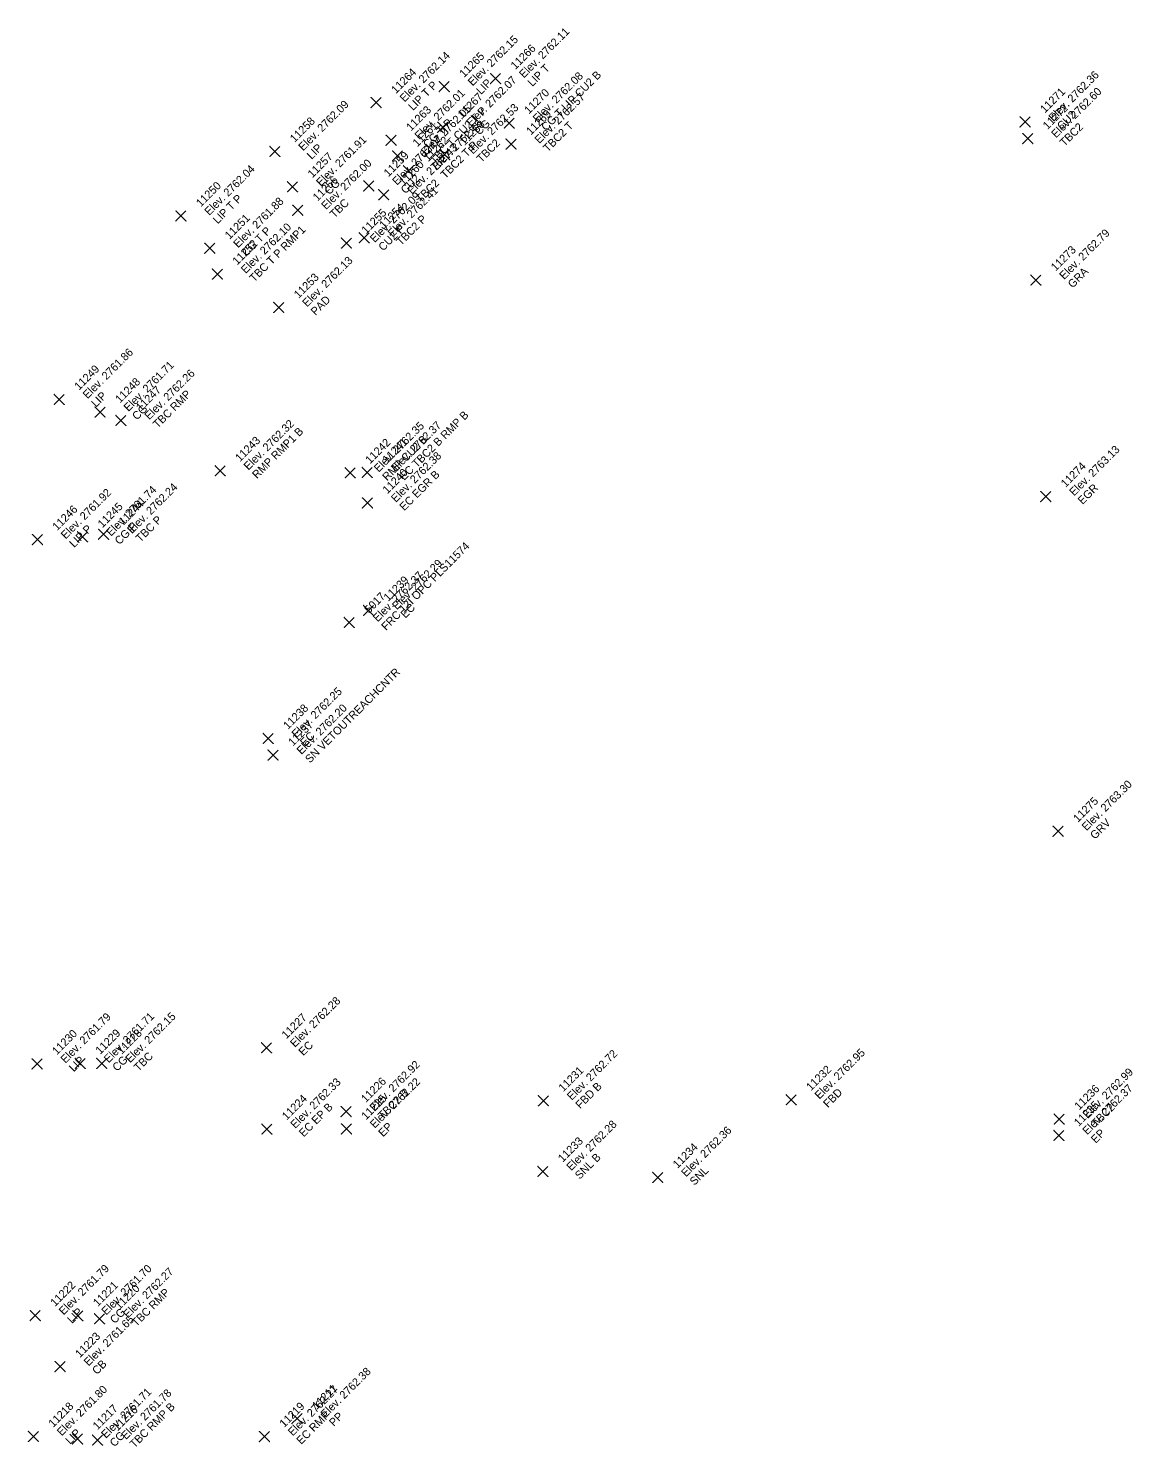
# Model space of a CAD drawing. Extents: x 2493999 to 2503109, y 700767 to 706646.
# Drawn here: x 2502307.24 to 2502340.35, y 701734.74 to 701777.28 of the extents above; entities that cross this region are included whole.
import ezdxf

# ---------------------------------------------------------------- set-up
doc = ezdxf.new("R2010")
doc.units = 0
doc.layers.add('ALG_CL_BLUE_Horiz', color=7, linetype='Continuous')
doc.layers.add('DES_SURFACE_Existing-Ground', color=7, linetype='Continuous')

msp = doc.modelspace()

# ---------------------------------------------------------------- linework, layer by layer
at = {"layer": 'ALG_CL_BLUE_Horiz'}
for points in [[(2502319.71, 701775.531), (2502319.56, 701775.681), (2502319.71, 701775.531), (2502319.56, 701775.381), (2502319.71, 701775.531), (2502319.86, 701775.381), (2502319.71, 701775.531), (2502319.86, 701775.681)], [(2502321.249, 701775.767), (2502321.099, 701775.917), (2502321.249, 701775.767), (2502321.099, 701775.617), (2502321.249, 701775.767), (2502321.399, 701775.617), (2502321.249, 701775.767), (2502321.399, 701775.917)], [(2502317.668, 701775.048), (2502317.518, 701775.198), (2502317.668, 701775.048), (2502317.518, 701774.898), (2502317.668, 701775.048), (2502317.818, 701774.898), (2502317.668, 701775.048), (2502317.818, 701775.198)], [(2502319.663, 701774.312), (2502319.513, 701774.462), (2502319.663, 701774.312), (2502319.513, 701774.162), (2502319.663, 701774.312), (2502319.813, 701774.162), (2502319.663, 701774.312), (2502319.813, 701774.462)], [(2502321.658, 701774.436), (2502321.508, 701774.586), (2502321.658, 701774.436), (2502321.508, 701774.286), (2502321.658, 701774.436), (2502321.808, 701774.286), (2502321.658, 701774.436), (2502321.808, 701774.586)], [(2502337.128, 701774.468), (2502336.978, 701774.618), (2502337.128, 701774.468), (2502336.978, 701774.318), (2502337.128, 701774.468), (2502337.278, 701774.318), (2502337.128, 701774.468), (2502337.278, 701774.618)], [(2502318.116, 701773.921), (2502317.966, 701774.071), (2502318.116, 701773.921), (2502317.966, 701773.771), (2502318.116, 701773.921), (2502318.266, 701773.771), (2502318.116, 701773.921), (2502318.266, 701774.071)], [(2502337.208, 701773.97), (2502337.058, 701774.12), (2502337.208, 701773.97), (2502337.058, 701773.82), (2502337.208, 701773.97), (2502337.358, 701773.82), (2502337.208, 701773.97), (2502337.358, 701774.12)], [(2502314.63, 701773.584), (2502314.48, 701773.734), (2502314.63, 701773.584), (2502314.48, 701773.434), (2502314.63, 701773.584), (2502314.78, 701773.434), (2502314.63, 701773.584), (2502314.78, 701773.734)], [(2502318.308, 701773.45), (2502318.158, 701773.6), (2502318.308, 701773.45), (2502318.158, 701773.3), (2502318.308, 701773.45), (2502318.458, 701773.3), (2502318.308, 701773.45), (2502318.458, 701773.6)], [(2502319.722, 701773.488), (2502319.572, 701773.638), (2502319.722, 701773.488), (2502319.572, 701773.338), (2502319.722, 701773.488), (2502319.872, 701773.338), (2502319.722, 701773.488), (2502319.872, 701773.638)], [(2502321.714, 701773.804), (2502321.564, 701773.954), (2502321.714, 701773.804), (2502321.564, 701773.654), (2502321.714, 701773.804), (2502321.864, 701773.654), (2502321.714, 701773.804), (2502321.864, 701773.954)], [(2502318.638, 701773.006), (2502318.488, 701773.156), (2502318.638, 701773.006), (2502318.488, 701772.856), (2502318.638, 701773.006), (2502318.788, 701772.856), (2502318.638, 701773.006), (2502318.788, 701773.156)], [(2502317.444, 701772.552), (2502317.294, 701772.702), (2502317.444, 701772.552), (2502317.294, 701772.402), (2502317.444, 701772.552), (2502317.594, 701772.402), (2502317.444, 701772.552), (2502317.594, 701772.702)], [(2502315.162, 701772.523), (2502315.012, 701772.673), (2502315.162, 701772.523), (2502315.012, 701772.373), (2502315.162, 701772.523), (2502315.312, 701772.373), (2502315.162, 701772.523), (2502315.312, 701772.673)], [(2502317.896, 701772.285), (2502317.746, 701772.435), (2502317.896, 701772.285), (2502317.746, 701772.135), (2502317.896, 701772.285), (2502318.046, 701772.135), (2502317.896, 701772.285), (2502318.046, 701772.435)], [(2502315.317, 701771.821), (2502315.167, 701771.971), (2502315.317, 701771.821), (2502315.167, 701771.671), (2502315.317, 701771.821), (2502315.467, 701771.671), (2502315.317, 701771.821), (2502315.467, 701771.971)], [(2502311.814, 701771.648), (2502311.664, 701771.798), (2502311.814, 701771.648), (2502311.664, 701771.498), (2502311.814, 701771.648), (2502311.964, 701771.498), (2502311.814, 701771.648), (2502311.964, 701771.798)], [(2502316.775, 701770.836), (2502316.625, 701770.986), (2502316.775, 701770.836), (2502316.625, 701770.686), (2502316.775, 701770.836), (2502316.925, 701770.686), (2502316.775, 701770.836), (2502316.925, 701770.986)], [(2502317.31, 701770.996), (2502317.16, 701771.146), (2502317.31, 701770.996), (2502317.16, 701770.846), (2502317.31, 701770.996), (2502317.46, 701770.846), (2502317.31, 701770.996), (2502317.46, 701771.146)], [(2502312.677, 701770.679), (2502312.527, 701770.829), (2502312.677, 701770.679), (2502312.527, 701770.529), (2502312.677, 701770.679), (2502312.827, 701770.529), (2502312.677, 701770.679), (2502312.827, 701770.829)], [(2502312.907, 701769.906), (2502312.757, 701770.056), (2502312.907, 701769.906), (2502312.757, 701769.756), (2502312.907, 701769.906), (2502313.057, 701769.756), (2502312.907, 701769.906), (2502313.057, 701770.056)], [(2502337.451, 701769.725), (2502337.301, 701769.875), (2502337.451, 701769.725), (2502337.301, 701769.575), (2502337.451, 701769.725), (2502337.601, 701769.575), (2502337.451, 701769.725), (2502337.601, 701769.875)], [(2502314.748, 701768.904), (2502314.598, 701769.054), (2502314.748, 701768.904), (2502314.598, 701768.754), (2502314.748, 701768.904), (2502314.898, 701768.754), (2502314.748, 701768.904), (2502314.898, 701769.054)], [(2502308.164, 701766.149), (2502308.014, 701766.299), (2502308.164, 701766.149), (2502308.014, 701765.999), (2502308.164, 701766.149), (2502308.314, 701765.999), (2502308.164, 701766.149), (2502308.314, 701766.299)], [(2502309.391, 701765.766), (2502309.241, 701765.916), (2502309.391, 701765.766), (2502309.241, 701765.616), (2502309.391, 701765.766), (2502309.541, 701765.616), (2502309.391, 701765.766), (2502309.541, 701765.916)], [(2502310.014, 701765.518), (2502309.864, 701765.668), (2502310.014, 701765.518), (2502309.864, 701765.368), (2502310.014, 701765.518), (2502310.164, 701765.368), (2502310.014, 701765.518), (2502310.164, 701765.668)], [(2502312.99, 701764.007), (2502312.84, 701764.157), (2502312.99, 701764.007), (2502312.84, 701763.857), (2502312.99, 701764.007), (2502313.14, 701763.857), (2502312.99, 701764.007), (2502313.14, 701764.157)], [(2502316.892, 701763.945), (2502316.742, 701764.095), (2502316.892, 701763.945), (2502316.742, 701763.795), (2502316.892, 701763.945), (2502317.042, 701763.795), (2502316.892, 701763.945), (2502317.042, 701764.095)], [(2502317.403, 701763.958), (2502317.253, 701764.108), (2502317.403, 701763.958), (2502317.253, 701763.808), (2502317.403, 701763.958), (2502317.553, 701763.808), (2502317.403, 701763.958), (2502317.553, 701764.108)], [(2502337.749, 701763.234), (2502337.599, 701763.384), (2502337.749, 701763.234), (2502337.599, 701763.084), (2502337.749, 701763.234), (2502337.899, 701763.084), (2502337.749, 701763.234), (2502337.899, 701763.384)], [(2502317.408, 701763.044), (2502317.258, 701763.194), (2502317.408, 701763.044), (2502317.258, 701762.894), (2502317.408, 701763.044), (2502317.558, 701762.894), (2502317.408, 701763.044), (2502317.558, 701763.194)], [(2502307.508, 701761.942), (2502307.358, 701762.092), (2502307.508, 701761.942), (2502307.358, 701761.792), (2502307.508, 701761.942), (2502307.658, 701761.792), (2502307.508, 701761.942), (2502307.658, 701762.092)], [(2502308.866, 701762.026), (2502308.716, 701762.176), (2502308.866, 701762.026), (2502308.716, 701761.876), (2502308.866, 701762.026), (2502309.016, 701761.876), (2502308.866, 701762.026), (2502309.016, 701762.176)], [(2502309.496, 701762.102), (2502309.346, 701762.252), (2502309.496, 701762.102), (2502309.346, 701761.952), (2502309.496, 701762.102), (2502309.646, 701761.952), (2502309.496, 701762.102), (2502309.646, 701762.252)], [(2502317.439, 701759.82), (2502317.289, 701759.97), (2502317.439, 701759.82), (2502317.289, 701759.67), (2502317.439, 701759.82), (2502317.589, 701759.67), (2502317.439, 701759.82), (2502317.589, 701759.97)], [(2502316.862, 701759.456), (2502316.712, 701759.606), (2502316.862, 701759.456), (2502316.712, 701759.306), (2502316.862, 701759.456), (2502317.012, 701759.306), (2502316.862, 701759.456), (2502317.012, 701759.606)], [(2502314.43, 701755.978), (2502314.28, 701756.128), (2502314.43, 701755.978), (2502314.28, 701755.828), (2502314.43, 701755.978), (2502314.58, 701755.828), (2502314.43, 701755.978), (2502314.58, 701756.128)], [(2502314.579, 701755.479), (2502314.429, 701755.629), (2502314.579, 701755.479), (2502314.429, 701755.329), (2502314.579, 701755.479), (2502314.729, 701755.329), (2502314.579, 701755.479), (2502314.729, 701755.629)], [(2502338.12, 701753.193), (2502337.97, 701753.343), (2502338.12, 701753.193), (2502337.97, 701753.043), (2502338.12, 701753.193), (2502338.27, 701753.043), (2502338.12, 701753.193), (2502338.27, 701753.343)], [(2502314.381, 701746.7), (2502314.231, 701746.85), (2502314.381, 701746.7), (2502314.231, 701746.55), (2502314.381, 701746.7), (2502314.531, 701746.55), (2502314.381, 701746.7), (2502314.531, 701746.85)], [(2502307.498, 701746.217), (2502307.348, 701746.367), (2502307.498, 701746.217), (2502307.348, 701746.067), (2502307.498, 701746.217), (2502307.648, 701746.067), (2502307.498, 701746.217), (2502307.648, 701746.367)], [(2502308.796, 701746.232), (2502308.646, 701746.382), (2502308.796, 701746.232), (2502308.646, 701746.082), (2502308.796, 701746.232), (2502308.946, 701746.082), (2502308.796, 701746.232), (2502308.946, 701746.382)], [(2502309.441, 701746.231), (2502309.291, 701746.381), (2502309.441, 701746.231), (2502309.291, 701746.081), (2502309.441, 701746.231), (2502309.591, 701746.081), (2502309.441, 701746.231), (2502309.591, 701746.381)], [(2502322.686, 701745.11), (2502322.536, 701745.26), (2502322.686, 701745.11), (2502322.536, 701744.96), (2502322.686, 701745.11), (2502322.836, 701744.96), (2502322.686, 701745.11), (2502322.836, 701745.26)], [(2502330.114, 701745.142), (2502329.964, 701745.292), (2502330.114, 701745.142), (2502329.964, 701744.992), (2502330.114, 701745.142), (2502330.264, 701744.992), (2502330.114, 701745.142), (2502330.264, 701745.292)], [(2502316.764, 701744.785), (2502316.614, 701744.935), (2502316.764, 701744.785), (2502316.614, 701744.635), (2502316.764, 701744.785), (2502316.914, 701744.635), (2502316.764, 701744.785), (2502316.914, 701744.935)], [(2502338.155, 701744.563), (2502338.005, 701744.713), (2502338.155, 701744.563), (2502338.005, 701744.413), (2502338.155, 701744.563), (2502338.305, 701744.413), (2502338.155, 701744.563), (2502338.305, 701744.713)], [(2502314.392, 701744.263), (2502314.242, 701744.413), (2502314.392, 701744.263), (2502314.242, 701744.113), (2502314.392, 701744.263), (2502314.542, 701744.113), (2502314.392, 701744.263), (2502314.542, 701744.413)], [(2502316.774, 701744.268), (2502316.624, 701744.418), (2502316.774, 701744.268), (2502316.624, 701744.118), (2502316.774, 701744.268), (2502316.924, 701744.118), (2502316.774, 701744.268), (2502316.924, 701744.418)], [(2502338.143, 701744.073), (2502337.993, 701744.223), (2502338.143, 701744.073), (2502337.993, 701743.923), (2502338.143, 701744.073), (2502338.293, 701743.923), (2502338.143, 701744.073), (2502338.293, 701744.223)], [(2502322.668, 701742.995), (2502322.518, 701743.145), (2502322.668, 701742.995), (2502322.518, 701742.845), (2502322.668, 701742.995), (2502322.818, 701742.845), (2502322.668, 701742.995), (2502322.818, 701743.145)], [(2502326.111, 701742.814), (2502325.961, 701742.964), (2502326.111, 701742.814), (2502325.961, 701742.664), (2502326.111, 701742.814), (2502326.261, 701742.664), (2502326.111, 701742.814), (2502326.261, 701742.964)], [(2502307.445, 701738.67), (2502307.295, 701738.82), (2502307.445, 701738.67), (2502307.295, 701738.52), (2502307.445, 701738.67), (2502307.595, 701738.52), (2502307.445, 701738.67), (2502307.595, 701738.82)], [(2502308.725, 701738.665), (2502308.575, 701738.815), (2502308.725, 701738.665), (2502308.575, 701738.515), (2502308.725, 701738.665), (2502308.875, 701738.515), (2502308.725, 701738.665), (2502308.875, 701738.815)], [(2502309.375, 701738.575), (2502309.225, 701738.725), (2502309.375, 701738.575), (2502309.225, 701738.425), (2502309.375, 701738.575), (2502309.525, 701738.425), (2502309.375, 701738.575), (2502309.525, 701738.725)], [(2502308.191, 701737.138), (2502308.041, 701737.288), (2502308.191, 701737.138), (2502308.041, 701736.988), (2502308.191, 701737.138), (2502308.341, 701736.988), (2502308.191, 701737.138), (2502308.341, 701737.288)], [(2502315.294, 701735.582), (2502315.144, 701735.732), (2502315.294, 701735.582), (2502315.144, 701735.432), (2502315.294, 701735.582), (2502315.444, 701735.432), (2502315.294, 701735.582), (2502315.444, 701735.732)], [(2502307.388, 701735.043), (2502307.238, 701735.193), (2502307.388, 701735.043), (2502307.238, 701734.893), (2502307.388, 701735.043), (2502307.538, 701734.893), (2502307.388, 701735.043), (2502307.538, 701735.193)], [(2502308.716, 701734.969), (2502308.566, 701735.119), (2502308.716, 701734.969), (2502308.566, 701734.819), (2502308.716, 701734.969), (2502308.866, 701734.819), (2502308.716, 701734.969), (2502308.866, 701735.119)], [(2502309.316, 701734.934), (2502309.166, 701735.084), (2502309.316, 701734.934), (2502309.166, 701734.784), (2502309.316, 701734.934), (2502309.466, 701734.784), (2502309.316, 701734.934), (2502309.466, 701735.084)], [(2502314.317, 701735.041), (2502314.167, 701735.191), (2502314.317, 701735.041), (2502314.167, 701734.891), (2502314.317, 701735.041), (2502314.467, 701734.891), (2502314.317, 701735.041), (2502314.467, 701735.191)]]:
    msp.add_lwpolyline(points, dxfattribs=at)

# ---------------------------------------------------------------- texts
at = {"layer": 'DES_SURFACE_Existing-Ground'}
for s, p in [('Elev. 2762.15', (2502320.559, 701775.531)), ('Elev. 2762.11', (2502322.098, 701775.767)), ('Elev. 2762.14', (2502318.517, 701775.048)), ('11265', (2502320.304, 701775.786)), ('11266', (2502321.843, 701776.022)), ('LIP T', (2502322.352, 701775.512)), ('11264', (2502318.262, 701775.303)), ('LIP T P', (2502318.771, 701774.793)), ('Elev. 2762.07', (2502320.512, 701774.312)), ('LIP', (2502320.813, 701775.276)), ('Elev. 2762.08', (2502322.507, 701774.436)), ('CG T LIP CU2 B', (2502322.761, 701774.181)), ('Elev. 2762.36', (2502337.977, 701774.468)), ('Elev. 2762.01', (2502318.965, 701773.921)), ('11267', (2502320.257, 701774.567)), ('11270', (2502322.252, 701774.691)), ('Elev. 2762.57', (2502322.563, 701773.804)), ('11271', (2502337.722, 701774.723)), ('Elev. 2762.60', (2502338.057, 701773.97)), ('Elev. 2762.09', (2502315.479, 701773.584)), ('11263', (2502318.71, 701774.176)), ('Elev. 2762.05', (2502319.157, 701773.45)), ('TBC T CU2 T P', (2502319.411, 701773.195)), ('Elev. 2762.53', (2502320.571, 701773.488)), ('11269', (2502322.308, 701774.059)), ('11272', (2502337.802, 701774.225)), ('11258', (2502315.224, 701773.839)), ('11261', (2502318.902, 701773.705)), ('CG T P', (2502319.219, 701773.666)), ('Elev. 2762.46', (2502319.487, 701773.006)), ('11268', (2502320.316, 701773.743)), ('CG', (2502320.766, 701774.057)), ('TBC2 T', (2502322.817, 701773.549)), ('CU2', (2502338.231, 701774.213)), ('TBC2', (2502338.311, 701773.715)), ('Elev. 2761.91', (2502316.011, 701772.523)), ('Elev. 2762.07', (2502318.293, 701772.552)), ('11262', (2502319.232, 701773.261)), ('LIP', (2502315.733, 701773.329)), ('11257', (2502315.756, 701772.778)), ('11259', (2502318.038, 701772.807)), ('Elev. 2762.43', (2502318.745, 701772.285)), ('TBC2 T P', (2502319.741, 701772.751)), ('TBC2', (2502320.825, 701773.233)), ('Elev. 2762.04', (2502312.663, 701771.648)), ('Elev. 2762.00', (2502316.166, 701771.821)), ('11260', (2502318.49, 701772.54)), ('11256', (2502315.911, 701772.076)), ('CG', (2502316.265, 701772.268)), ('CU2', (2502318.547, 701772.297)), ('TBC2', (2502318.999, 701772.03)), ('11250', (2502312.408, 701771.903)), ('LIP T P', (2502312.917, 701771.393)), ('Elev. 2762.09', (2502317.624, 701770.836)), ('Elev. 2762.41', (2502318.159, 701770.996)), ('Elev. 2761.88', (2502313.526, 701770.679)), ('TBC', (2502316.42, 701771.566)), ('11255', (2502317.369, 701771.091)), ('11254', (2502317.904, 701771.251)), ('11251', (2502313.271, 701770.934)), ('Elev. 2762.10', (2502313.756, 701769.906)), ('TBC2 P', (2502318.413, 701770.741)), ('CG T P', (2502313.78, 701770.424)), ('TBC T P RMP1', (2502314.01, 701769.651)), ('CU2 P', (2502317.878, 701770.581)), ('Elev. 2762.79', (2502338.3, 701769.725)), ('11252', (2502313.501, 701770.161)), ('11273', (2502338.045, 701769.98)), ('Elev. 2762.13', (2502315.597, 701768.904)), ('11253', (2502315.342, 701769.159)), ('GRA', (2502338.554, 701769.47)), ('PAD', (2502315.851, 701768.649)), ('Elev. 2761.86', (2502309.013, 701766.149)), ('11249', (2502308.758, 701766.404)), ('Elev. 2761.71', (2502310.24, 701765.766)), ('11248', (2502309.985, 701766.021)), ('Elev. 2762.26', (2502310.863, 701765.518)), ('LIP', (2502309.267, 701765.894)), ('11247', (2502310.608, 701765.773)), ('TBC RMP', (2502311.117, 701765.263)), ('CG', (2502310.494, 701765.511)), ('Elev. 2762.32', (2502313.839, 701764.007)), ('Elev. 2762.35', (2502317.741, 701763.945)), ('Elev. 2762.37', (2502318.252, 701763.958)), ('EC TBC2 B RMP B', (2502318.506, 701763.703)), ('RMP RMP1 B', (2502314.093, 701763.752)), ('RMP CU2 B', (2502317.995, 701763.69)), ('11243', (2502313.584, 701764.262)), ('11242', (2502317.486, 701764.2)), ('11241', (2502317.997, 701764.213)), ('Elev. 2763.13', (2502338.598, 701763.234)), ('Elev. 2762.38', (2502318.257, 701763.044)), ('11274', (2502338.343, 701763.489)), ('11240', (2502318.002, 701763.299)), ('EC EGR B', (2502318.511, 701762.789)), ('Elev. 2761.92', (2502308.357, 701761.942)), ('Elev. 2761.74', (2502309.715, 701762.026)), ('Elev. 2762.24', (2502310.345, 701762.102)), ('EGR', (2502338.852, 701762.979)), ('11246', (2502308.102, 701762.197)), ('11245', (2502309.46, 701762.281)), ('11244', (2502310.09, 701762.357)), ('TBC P', (2502310.599, 701761.847)), ('LIP P', (2502308.611, 701761.687)), ('CG P', (2502309.969, 701761.771)), ('FRC 12I OPC PLS11574', (2502317.965, 701759.201)), ('Elev. 2762.29', (2502318.288, 701759.82)), ('Elev. 2762.37', (2502317.711, 701759.456)), ('11239', (2502318.033, 701760.075)), ('5017', (2502317.456, 701759.711)), ('EC', (2502318.542, 701759.565)), ('SN VETOUTREACHCNTR', (2502315.682, 701755.224)), ('Elev. 2762.25', (2502315.279, 701755.978)), ('11238', (2502315.024, 701756.233)), ('Elev. 2762.20', (2502315.428, 701755.479)), ('11237', (2502315.173, 701755.734)), ('EC', (2502315.533, 701755.723)), ('Elev. 2763.30', (2502338.969, 701753.193)), ('11275', (2502338.714, 701753.448)), ('GRV', (2502339.223, 701752.938)), ('Elev. 2762.28', (2502315.23, 701746.7)), ('Elev. 2761.79', (2502308.347, 701746.217)), ('Elev. 2761.71', (2502309.645, 701746.232)), ('Elev. 2762.15', (2502310.29, 701746.231)), ('11227', (2502314.975, 701746.955)), ('11230', (2502308.092, 701746.472)), ('11229', (2502309.39, 701746.487)), ('11228', (2502310.035, 701746.486)), ('EC', (2502315.484, 701746.445)), ('LIP', (2502308.601, 701745.962)), ('CG', (2502309.899, 701745.977)), ('TBC', (2502310.544, 701745.976)), ('Elev. 2762.72', (2502323.535, 701745.11)), ('Elev. 2762.95', (2502330.963, 701745.142)), ('Elev. 2762.92', (2502317.613, 701744.785)), ('11231', (2502323.28, 701745.365)), ('11232', (2502330.708, 701745.397)), ('Elev. 2762.99', (2502339.004, 701744.563)), ('Elev. 2762.33', (2502315.241, 701744.263)), ('11226', (2502317.358, 701745.04)), ('Elev. 2762.22', (2502317.623, 701744.268)), ('TBC2 B', (2502317.867, 701744.53)), ('FBD B', (2502323.789, 701744.855)), ('11236', (2502338.749, 701744.818)), ('Elev. 2762.37', (2502338.992, 701744.073)), ('11224', (2502314.986, 701744.518)), ('EC EP B', (2502315.495, 701744.008)), ('11225', (2502317.368, 701744.523)), ('FBD', (2502331.217, 701744.887)), ('11235', (2502338.737, 701744.328)), ('TBC2', (2502339.258, 701744.308)), ('EP', (2502317.877, 701744.013)), ('Elev. 2762.28', (2502323.517, 701742.995)), ('Elev. 2762.36', (2502326.96, 701742.814)), ('EP', (2502339.246, 701743.818)), ('11233', (2502323.262, 701743.25)), ('11234', (2502326.705, 701743.069)), ('SNL B', (2502323.771, 701742.74)), ('SNL', (2502327.214, 701742.559)), ('Elev. 2761.79', (2502308.294, 701738.67)), ('Elev. 2761.70', (2502309.574, 701738.665)), ('Elev. 2762.27', (2502310.224, 701738.575)), ('11222', (2502308.039, 701738.925)), ('11221', (2502309.319, 701738.92)), ('11220', (2502309.969, 701738.83)), ('TBC RMP', (2502310.478, 701738.32)), ('LIP', (2502308.548, 701738.415)), ('Elev. 2761.65', (2502309.04, 701737.138)), ('CG', (2502309.828, 701738.41)), ('11223', (2502308.785, 701737.393)), ('CB', (2502309.294, 701736.883)), ('Elev. 2762.38', (2502316.143, 701735.582)), ('Elev. 2761.80', (2502308.237, 701735.043)), ('Elev. 2762.27', (2502315.166, 701735.041)), ('11211', (2502315.888, 701735.837)), ('Elev. 2761.71', (2502309.565, 701734.969)), ('Elev. 2761.78', (2502310.165, 701734.934)), ('11218', (2502307.982, 701735.298)), ('11217', (2502309.31, 701735.224)), ('11216', (2502309.91, 701735.189)), ('TBC RMP B', (2502310.419, 701734.679)), ('11219', (2502314.911, 701735.296)), ('EC RMP', (2502315.42, 701734.786)), ('PP', (2502316.397, 701735.327)), ('LIP', (2502308.491, 701734.788)), ('CG', (2502309.819, 701734.714))]:
    msp.add_text(s, height=0.24, rotation=45, dxfattribs=at).set_placement(p)

doc.saveas('drawing.dxf')
